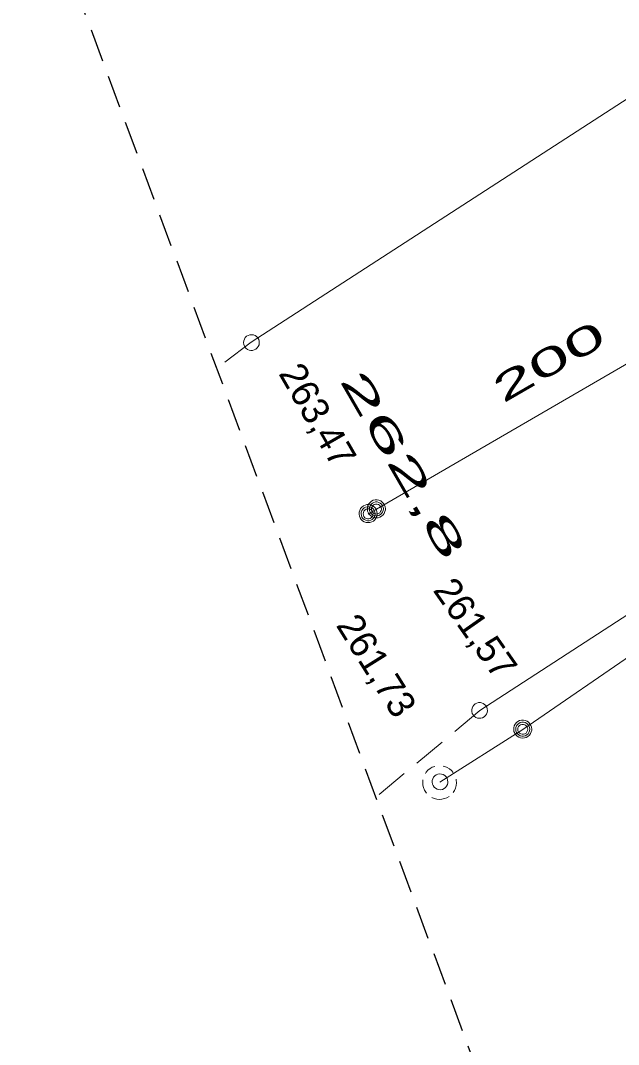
# Model space of a CAD drawing. Extents: x -732074 to -731966, y -1048695 to -1047982.
# Drawn here: x -732041.63 to -732024.14, y -1048122.14 to -1048092.2 of the extents above; entities that cross this region are included whole.
import ezdxf

# ---------------------------------------------------------------- set-up
doc = ezdxf.new("R2010")
doc.units = 0
doc.header["$LTSCALE"] = 0.32
doc.linetypes.add('MEDIUM_DASHED', pattern=[4.5, 3, -1.5])
doc.layers.add('1', color=7, linetype='Continuous')
for name, color, linetype, lineweight in [('18', 7, 'Continuous', 13), ('49', 7, 'Continuous', 13), ('63', 7, 'MEDIUM_DASHED', 25), ('8', 7, 'Continuous', 13)]:
    doc.layers.add(name, color=color, linetype=linetype, lineweight=lineweight)

msp = doc.modelspace()

# ---------------------------------------------------------------- linework, layer by layer
at = {"layer": '18'}
for points in [[(-732031.196, -1048106.617), (-732031.201, -1048106.561), (-732031.218, -1048106.508), (-732031.247, -1048106.459), (-732031.286, -1048106.418), (-732031.331, -1048106.386), (-732031.384, -1048106.364), (-732031.439, -1048106.353), (-732031.495, -1048106.355), (-732031.549, -1048106.368), (-732031.6, -1048106.393), (-732031.645, -1048106.428), (-732031.681, -1048106.471), (-732031.706, -1048106.521), (-732031.721, -1048106.576), (-732031.723, -1048106.632), (-732031.715, -1048106.687), (-732031.694, -1048106.74), (-732031.663, -1048106.786), (-732031.622, -1048106.825), (-732031.575, -1048106.855), (-732031.522, -1048106.874), (-732031.466, -1048106.881), (-732031.409, -1048106.877), (-732031.355, -1048106.86), (-732031.306, -1048106.833), (-732031.265, -1048106.795), (-732031.232, -1048106.75), (-732031.208, -1048106.699), (-732031.196, -1048106.644)], [(-732031.255, -1048106.62), (-732031.261, -1048106.571), (-732031.279, -1048106.525), (-732031.306, -1048106.484), (-732031.343, -1048106.451), (-732031.387, -1048106.429), (-732031.436, -1048106.417), (-732031.485, -1048106.417), (-732031.532, -1048106.429), (-732031.576, -1048106.452), (-732031.614, -1048106.485), (-732031.642, -1048106.526), (-732031.659, -1048106.573), (-732031.664, -1048106.622), (-732031.657, -1048106.671), (-732031.64, -1048106.717), (-732031.612, -1048106.757), (-732031.575, -1048106.79), (-732031.531, -1048106.812), (-732031.482, -1048106.824), (-732031.433, -1048106.823), (-732031.385, -1048106.811), (-732031.342, -1048106.787), (-732031.304, -1048106.754), (-732031.277, -1048106.713), (-732031.261, -1048106.666)], [(-732031.314, -1048106.624), (-732031.32, -1048106.582), (-732031.337, -1048106.544), (-732031.365, -1048106.513), (-732031.399, -1048106.49), (-732031.44, -1048106.479), (-732031.482, -1048106.479), (-732031.522, -1048106.491), (-732031.556, -1048106.514), (-732031.583, -1048106.546), (-732031.6, -1048106.584), (-732031.605, -1048106.625), (-732031.6, -1048106.667), (-732031.581, -1048106.704), (-732031.554, -1048106.736), (-732031.517, -1048106.758), (-732031.478, -1048106.769), (-732031.436, -1048106.768), (-732031.396, -1048106.755), (-732031.362, -1048106.732), (-732031.335, -1048106.699), (-732031.319, -1048106.661)], [(-732030.955, -1048106.477), (-732030.961, -1048106.421), (-732030.978, -1048106.368), (-732031.007, -1048106.319), (-732031.045, -1048106.278), (-732031.091, -1048106.246), (-732031.143, -1048106.224), (-732031.198, -1048106.213), (-732031.254, -1048106.215), (-732031.309, -1048106.228), (-732031.36, -1048106.253), (-732031.404, -1048106.288), (-732031.44, -1048106.331), (-732031.465, -1048106.381), (-732031.48, -1048106.436), (-732031.483, -1048106.492), (-732031.474, -1048106.547), (-732031.453, -1048106.6), (-732031.422, -1048106.646), (-732031.382, -1048106.685), (-732031.334, -1048106.715), (-732031.281, -1048106.734), (-732031.225, -1048106.741), (-732031.169, -1048106.737), (-732031.115, -1048106.72), (-732031.066, -1048106.693), (-732031.024, -1048106.655), (-732030.991, -1048106.61), (-732030.968, -1048106.559), (-732030.956, -1048106.504)], [(-732031.014, -1048106.48), (-732031.02, -1048106.431), (-732031.038, -1048106.385), (-732031.066, -1048106.344), (-732031.103, -1048106.311), (-732031.147, -1048106.289), (-732031.195, -1048106.277), (-732031.244, -1048106.277), (-732031.292, -1048106.289), (-732031.336, -1048106.312), (-732031.373, -1048106.345), (-732031.401, -1048106.386), (-732031.418, -1048106.433), (-732031.424, -1048106.482), (-732031.417, -1048106.531), (-732031.399, -1048106.577), (-732031.371, -1048106.617), (-732031.334, -1048106.65), (-732031.29, -1048106.672), (-732031.241, -1048106.684), (-732031.192, -1048106.683), (-732031.144, -1048106.671), (-732031.101, -1048106.647), (-732031.064, -1048106.614), (-732031.036, -1048106.573), (-732031.02, -1048106.526)], [(-732031.073, -1048106.484), (-732031.079, -1048106.442), (-732031.096, -1048106.404), (-732031.124, -1048106.373), (-732031.159, -1048106.35), (-732031.199, -1048106.339), (-732031.241, -1048106.339), (-732031.281, -1048106.351), (-732031.316, -1048106.374), (-732031.343, -1048106.406), (-732031.36, -1048106.444), (-732031.365, -1048106.485), (-732031.359, -1048106.527), (-732031.341, -1048106.564), (-732031.313, -1048106.596), (-732031.277, -1048106.618), (-732031.237, -1048106.629), (-732031.195, -1048106.628), (-732031.155, -1048106.615), (-732031.121, -1048106.592), (-732031.094, -1048106.559), (-732031.078, -1048106.521)], [(-732026.676, -1048112.917), (-732026.681, -1048112.861), (-732026.698, -1048112.808), (-732026.727, -1048112.759), (-732026.766, -1048112.718), (-732026.811, -1048112.686), (-732026.864, -1048112.664), (-732026.919, -1048112.653), (-732026.975, -1048112.655), (-732027.029, -1048112.668), (-732027.08, -1048112.693), (-732027.125, -1048112.728), (-732027.161, -1048112.771), (-732027.186, -1048112.821), (-732027.201, -1048112.876), (-732027.203, -1048112.932), (-732027.195, -1048112.987), (-732027.174, -1048113.04), (-732027.142, -1048113.086), (-732027.102, -1048113.125), (-732027.054, -1048113.155), (-732027.002, -1048113.174), (-732026.946, -1048113.181), (-732026.889, -1048113.177), (-732026.835, -1048113.16), (-732026.786, -1048113.133), (-732026.745, -1048113.095), (-732026.712, -1048113.05), (-732026.688, -1048112.999), (-732026.676, -1048112.944)], [(-732026.735, -1048112.92), (-732026.74, -1048112.871), (-732026.759, -1048112.825), (-732026.786, -1048112.784), (-732026.823, -1048112.751), (-732026.867, -1048112.729), (-732026.916, -1048112.717), (-732026.965, -1048112.717), (-732027.012, -1048112.729), (-732027.056, -1048112.752), (-732027.093, -1048112.785), (-732027.122, -1048112.826), (-732027.139, -1048112.873), (-732027.144, -1048112.922), (-732027.137, -1048112.971), (-732027.12, -1048113.017), (-732027.092, -1048113.057), (-732027.054, -1048113.09), (-732027.011, -1048113.112), (-732026.962, -1048113.124), (-732026.913, -1048113.123), (-732026.865, -1048113.111), (-732026.821, -1048113.087), (-732026.784, -1048113.054), (-732026.757, -1048113.013), (-732026.74, -1048112.966)], [(-732026.794, -1048112.924), (-732026.799, -1048112.882), (-732026.816, -1048112.844), (-732026.845, -1048112.813), (-732026.879, -1048112.79), (-732026.919, -1048112.779), (-732026.962, -1048112.779), (-732027.002, -1048112.791), (-732027.036, -1048112.814), (-732027.063, -1048112.846), (-732027.08, -1048112.884), (-732027.085, -1048112.925), (-732027.08, -1048112.967), (-732027.061, -1048113.004), (-732027.034, -1048113.036), (-732026.997, -1048113.058), (-732026.958, -1048113.069), (-732026.916, -1048113.068), (-732026.875, -1048113.055), (-732026.842, -1048113.032), (-732026.815, -1048112.999), (-732026.799, -1048112.961)], [(-732029.128, -1048114.459), (-732029.134, -1048114.407), (-732029.152, -1048114.357), (-732029.18, -1048114.313), (-732029.218, -1048114.276), (-732029.263, -1048114.249), (-732029.313, -1048114.233), (-732029.365, -1048114.228), (-732029.417, -1048114.235), (-732029.466, -1048114.254), (-732029.51, -1048114.284), (-732029.545, -1048114.323), (-732029.571, -1048114.368), (-732029.586, -1048114.419), (-732029.589, -1048114.471), (-732029.581, -1048114.523), (-732029.56, -1048114.571), (-732029.53, -1048114.614), (-732029.49, -1048114.649), (-732029.444, -1048114.673), (-732029.393, -1048114.687), (-732029.341, -1048114.689), (-732029.289, -1048114.679), (-732029.241, -1048114.657), (-732029.199, -1048114.625), (-732029.166, -1048114.585), (-732029.142, -1048114.538), (-732029.13, -1048114.487)]]:
    msp.add_lwpolyline(points, close=True, dxfattribs=at)
for points in [[(-732029.512, -1048114.007), (-732029.583, -1048114.035), (-732029.65, -1048114.074), (-732029.71, -1048114.122), (-732029.761, -1048114.179), (-732029.785, -1048114.213)], [(-732028.971, -1048114.19), (-732029.021, -1048114.132), (-732029.079, -1048114.082), (-732029.144, -1048114.041), (-732029.215, -1048114.012), (-732029.264, -1048113.998)], [(-732029.857, -1048114.399), (-732029.863, -1048114.476), (-732029.858, -1048114.553), (-732029.841, -1048114.628), (-732029.812, -1048114.699), (-732029.772, -1048114.765), (-732029.756, -1048114.787)], [(-732028.976, -1048114.776), (-732028.935, -1048114.711), (-732028.904, -1048114.641), (-732028.885, -1048114.566), (-732028.877, -1048114.49), (-732028.882, -1048114.413), (-732028.888, -1048114.378)], [(-732029.599, -1048114.916), (-732029.529, -1048114.947), (-732029.454, -1048114.966), (-732029.378, -1048114.973), (-732029.301, -1048114.968), (-732029.226, -1048114.951), (-732029.154, -1048114.923), (-732029.094, -1048114.888)]]:
    msp.add_lwpolyline(points, dxfattribs=at)
at = {"layer": '49'}
for p, q in [((-732031.219, -1048106.49), (-732015.041, -1048097.097)), ((-732031.219, -1048106.49), (-732015.041, -1048097.097)), ((-732026.94, -1048112.93), (-732011.701, -1048102.444)), ((-732026.94, -1048112.93), (-732011.701, -1048102.444)), ((-732031.46, -1048106.63), (-732031.219, -1048106.49)), ((-732031.46, -1048106.63), (-732031.219, -1048106.49)), ((-732029.359, -1048114.47), (-732026.94, -1048112.93)), ((-732029.359, -1048114.47), (-732026.94, -1048112.93))]:
    msp.add_line(p, q, dxfattribs=at)
at = {"layer": '63'}
msp.add_lwpolyline([(-732069.268, -1048320.571), (-732031.703, -1048203.502), (-732026.193, -1048128.486), (-732054.591, -1048051.968)], dxfattribs=at)
at = {"layer": '8', "linetype": 'MEDIUM_DASHED'}
for p, q in [((-732034.879, -1048101.607), (-732035.888, -1048102.365)), ((-732028.191, -1048112.374), (-732031.232, -1048114.91))]:
    msp.add_line(p, q, dxfattribs=at)
at = {"layer": '8'}
msp.add_line((-732014, -1048103.16), (-732028.191, -1048112.374), dxfattribs=at)
msp.add_lwpolyline([(-732021.3, -1048092.69), (-732021.84, -1048093.16), (-732034.879, -1048101.607)], dxfattribs=at)
for points in [[(-732035.067, -1048101.741), (-732035.033, -1048101.781), (-732034.991, -1048101.814), (-732034.943, -1048101.835), (-732034.891, -1048101.846), (-732034.839, -1048101.844), (-732034.788, -1048101.83), (-732034.742, -1048101.806), (-732034.702, -1048101.772), (-732034.671, -1048101.729), (-732034.651, -1048101.68), (-732034.643, -1048101.628), (-732034.645, -1048101.576), (-732034.661, -1048101.525), (-732034.686, -1048101.48), (-732034.721, -1048101.441), (-732034.765, -1048101.412), (-732034.814, -1048101.392), (-732034.866, -1048101.385), (-732034.918, -1048101.39), (-732034.968, -1048101.406), (-732035.013, -1048101.432), (-732035.051, -1048101.469), (-732035.08, -1048101.514), (-732035.097, -1048101.563), (-732035.103, -1048101.615), (-732035.098, -1048101.667), (-732035.08, -1048101.717)], [(-732028.177, -1048112.143), (-732028.229, -1048112.143), (-732028.281, -1048112.156), (-732028.327, -1048112.179), (-732028.368, -1048112.213), (-732028.4, -1048112.255), (-732028.421, -1048112.303), (-732028.431, -1048112.354), (-732028.43, -1048112.406), (-732028.416, -1048112.457), (-732028.391, -1048112.504), (-732028.356, -1048112.543), (-732028.314, -1048112.574), (-732028.265, -1048112.594), (-732028.213, -1048112.602), (-732028.161, -1048112.6), (-732028.111, -1048112.584), (-732028.065, -1048112.559), (-732028.026, -1048112.523), (-732027.997, -1048112.479), (-732027.978, -1048112.43), (-732027.97, -1048112.379), (-732027.975, -1048112.326), (-732027.992, -1048112.276), (-732028.019, -1048112.231), (-732028.055, -1048112.194), (-732028.099, -1048112.165), (-732028.149, -1048112.148)]]:
    msp.add_lwpolyline(points, close=True, dxfattribs=at)

# ---------------------------------------------------------------- texts
at = {"layer": '1'}
for s, rotation, width, p in [('200 ', 30, 2, (-732027.519, -1048103.407)), ('262,8 ', 300, 2.3, (-732032.313, -1048102.716))]:
    msp.add_text(s, height=0.8, rotation=rotation, dxfattribs=dict(at, width=width)).set_placement(p)
for s, rotation, p in [('263,47', 300, (-732034.094, -1048102.519)), ('261,57', 305, (-732029.583, -1048108.859)), ('261,73', 302, (-732032.416, -1048109.881))]:
    msp.add_text(s, height=0.8, rotation=rotation, dxfattribs=at).set_placement(p)

doc.saveas('drawing.dxf')
